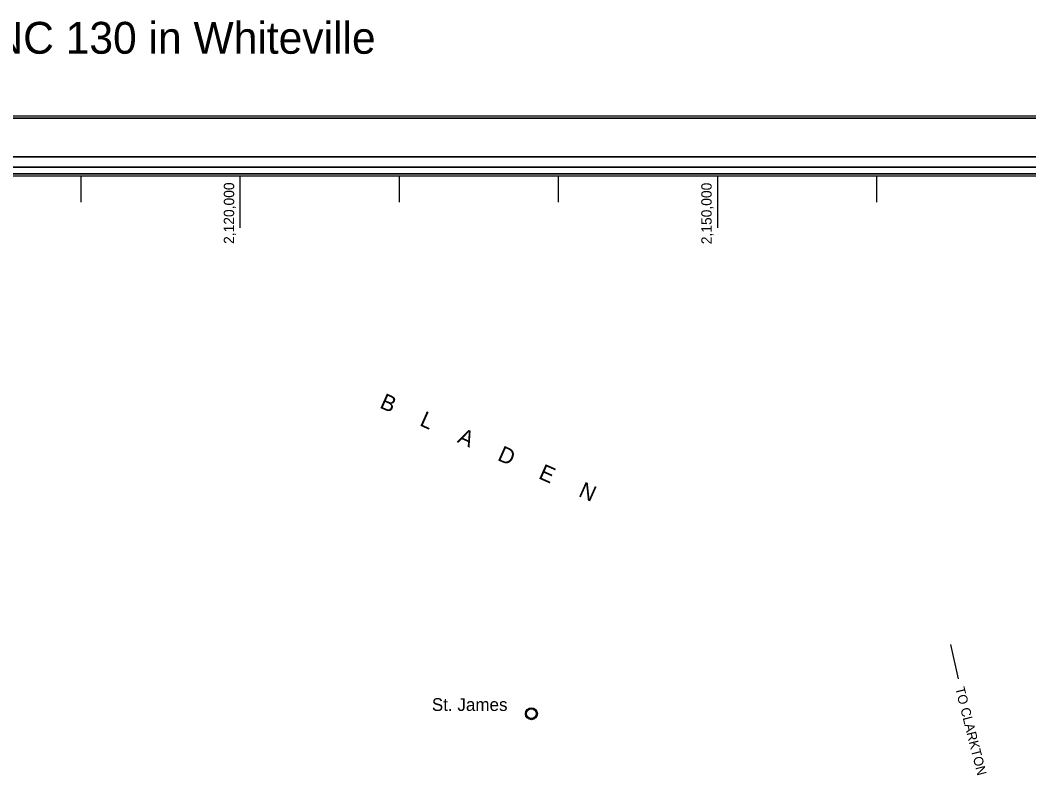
# Model space of a CAD drawing. Extents: x 5197761 to 5514561, y 1890130 to 2080942.
# Drawn here: x 5336955 to 5400329, y 2033240 to 2080942 of the extents above; entities that cross this region are included whole.
import ezdxf

# ---------------------------------------------------------------- set-up
doc = ezdxf.new("R2010")
doc.units = 0
for name, color, linetype in [('Exist Civil Demographics Community CELL', 7, 'Continuous'), ('Exist Civil Demographics Community Label', 7, 'Continuous'), ('Map Preparation Base StatePlane Tick Label', 7, 'Continuous'), ('Map Preparation Base StatePlane Tick Mark', 7, 'Continuous'), ('Map Preparation Border Antique Large Shape', 7, 'Continuous'), ('Map Preparation Border Antique Small Shape', 7, 'Continuous'), ('Map Preparation Border Black Inside Shape', 7, 'Continuous'), ('Map Preparation Border Black Middle Shape', 7, 'Continuous'), ('Map Preparation Border Black Outside Shape', 7, 'Continuous'), ('Map Preparation County Outside Label', 7, 'Continuous'), ('Map Preparation Destination Label', 7, 'Continuous'), ('Temp External Data Misc', 7, 'Continuous')]:
    doc.layers.add(name, color=color, linetype=linetype)

msp = doc.modelspace()

# ---------------------------------------------------------------- linework, layer by layer
at = {"layer": 'Exist Civil Demographics Community CELL'}
msp.add_lwpolyline([(5368766, 2037438), (5368770, 2037461), (5368777, 2037487), (5368789, 2037516), (5368801, 2037539), (5368814, 2037562), (5368829, 2037582), (5368845, 2037600), (5368863, 2037618), (5368886, 2037637), (5368907, 2037651), (5368927, 2037663), (5368947, 2037672), (5368969, 2037682), (5368991, 2037689), (5369009, 2037694), (5369028, 2037696), (5369045, 2037699), (5369070, 2037700), (5369088, 2037700), (5369110, 2037699), (5369130, 2037696), (5369150, 2037692), (5369170, 2037686), (5369190, 2037679), (5369217, 2037667), (5369242, 2037653), (5369262, 2037639), (5369283, 2037623), (5369296, 2037610), (5369313, 2037593), (5369328, 2037574), (5369340, 2037556), (5369353, 2037536), (5369363, 2037515), (5369371, 2037495), (5369377, 2037475), (5369382, 2037456), (5369387, 2037432), (5369389, 2037413), (5369390, 2037389), (5369389, 2037366), (5369387, 2037344), (5369383, 2037322), (5369377, 2037297), (5369369, 2037274), (5369360, 2037253), (5369348, 2037229), (5369334, 2037208), (5369321, 2037189), (5369304, 2037170), (5369283, 2037150), (5369262, 2037134), (5369242, 2037120), (5369225, 2037110), (5369198, 2037097), (5369169, 2037086), (5369145, 2037081), (5369119, 2037075), (5369101, 2037073), (5369083, 2037072), (5369061, 2037072), (5369044, 2037074), (5369021, 2037077), (5368998, 2037082), (5368979, 2037087), (5368959, 2037095), (5368940, 2037103), (5368925, 2037112), (5368897, 2037128), (5368875, 2037145), (5368855, 2037163), (5368838, 2037183), (5368825, 2037198), (5368813, 2037215), (5368797, 2037244), (5368790, 2037258), (5368783, 2037274), (5368773, 2037307), (5368766, 2037335), (5368764, 2037355), (5368762, 2037381), (5368762, 2037399), (5368764, 2037425)], close=True, dxfattribs=at)
for centre, radius in [((5369077, 2037389), 377), ((5369076, 2037390), 307)]:
    msp.add_circle(centre, radius, dxfattribs=at)
at = {"layer": 'Map Preparation Base StatePlane Tick Mark'}
for p, q in [((5340787, 2069519), (5340787, 2071145)), ((5350787, 2067894), (5350787, 2071145)), ((5360787, 2069519), (5360787, 2071145)), ((5370787, 2069519), (5370787, 2071145)), ((5380787, 2067894), (5380787, 2071145)), ((5390787, 2069519), (5390787, 2071145))]:
    msp.add_line(p, q, dxfattribs=at)
at = {"layer": 'Map Preparation Border Antique Large Shape'}
msp.add_lwpolyline([(5197907, 2074783), (5207205, 2074783), (5207205, 1892697), (5512539, 1892697), (5512539, 2072359), (5207205, 2072359), (5207205, 2074783), (5514414, 2074783), (5514414, 1890276), (5197907, 1890276)], close=True, dxfattribs=at)
at = {"layer": 'Map Preparation Border Antique Small Shape'}
msp.add_lwpolyline([(5207791, 2071720), (5208220, 2071720), (5208220, 1893712), (5511524, 1893712), (5511524, 2071291), (5208220, 2071291), (5208220, 2071720), (5207791, 2071720), (5511953, 2071720), (5511953, 1893283), (5208220, 1893283), (5207791, 1893283)], close=True, dxfattribs=at)
at = {"layer": 'Map Preparation Border Black Inside Shape'}
msp.add_lwpolyline([(5208220, 2071291), (5511524, 2071291), (5511524, 1893712), (5208366, 1893712), (5208366, 1893858), (5511378, 1893858), (5511378, 2071145), (5208366, 2071145), (5208366, 1893858), (5208366, 1893712), (5208220, 1893712), (5208220, 1893858)], close=True, dxfattribs=at)
at = {"layer": 'Map Preparation Border Black Middle Shape'}
msp.add_lwpolyline([(5207205, 2072359), (5512539, 2072359), (5512539, 1892697), (5511953, 1892697), (5207791, 1892697), (5207791, 1893283), (5511953, 1893283), (5511953, 2071720), (5207791, 2071720), (5207791, 1892697), (5207205, 1892697)], close=True, dxfattribs=at)
at = {"layer": 'Map Preparation Border Black Outside Shape'}
msp.add_lwpolyline([(5197761, 2074930), (5514561, 2074930), (5514561, 1890130), (5197907, 1890130), (5197907, 1890276), (5514414, 1890276), (5514414, 2074783), (5197907, 2074783), (5197907, 1890130), (5197761, 1890130)], close=True, dxfattribs=at)
at = {"layer": 'Map Preparation Destination Label'}
msp.add_line((5395405, 2041731), (5395882, 2039587), dxfattribs=at)

# ---------------------------------------------------------------- texts
at = {"layer": 'Exist Civil Demographics Community Label'}
msp.add_text('St. James', height=800, dxfattribs=at).set_placement((5362821, 2037564))
at = {"layer": 'Map Preparation Base StatePlane Tick Label'}
for s, p in [('2,120,000', (5350400, 2066889)), ('2,150,000', (5380400, 2066871))]:
    msp.add_text(s, height=650, rotation=90, dxfattribs=at).set_placement(p)
at = {"layer": 'Map Preparation County Outside Label'}
msp.add_text('B     L     A     D     E     N', height=1000, rotation=336.01512, dxfattribs=at).set_placement((5359487, 2056630))
at = {"layer": 'Map Preparation Destination Label'}
msp.add_text('TO CLARKTON', height=600, rotation=284.35537, dxfattribs=at).set_placement((5395693, 2038992))
at = {"layer": 'Temp External Data Misc'}
msp.add_text('HOLDING PBYP 701 and BUS 74/70 and NC 130 in Whiteville', height=2000, dxfattribs=at).set_placement((5285110, 2078835))

doc.saveas('drawing.dxf')
